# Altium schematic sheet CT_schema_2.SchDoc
size 461 x 327 mm
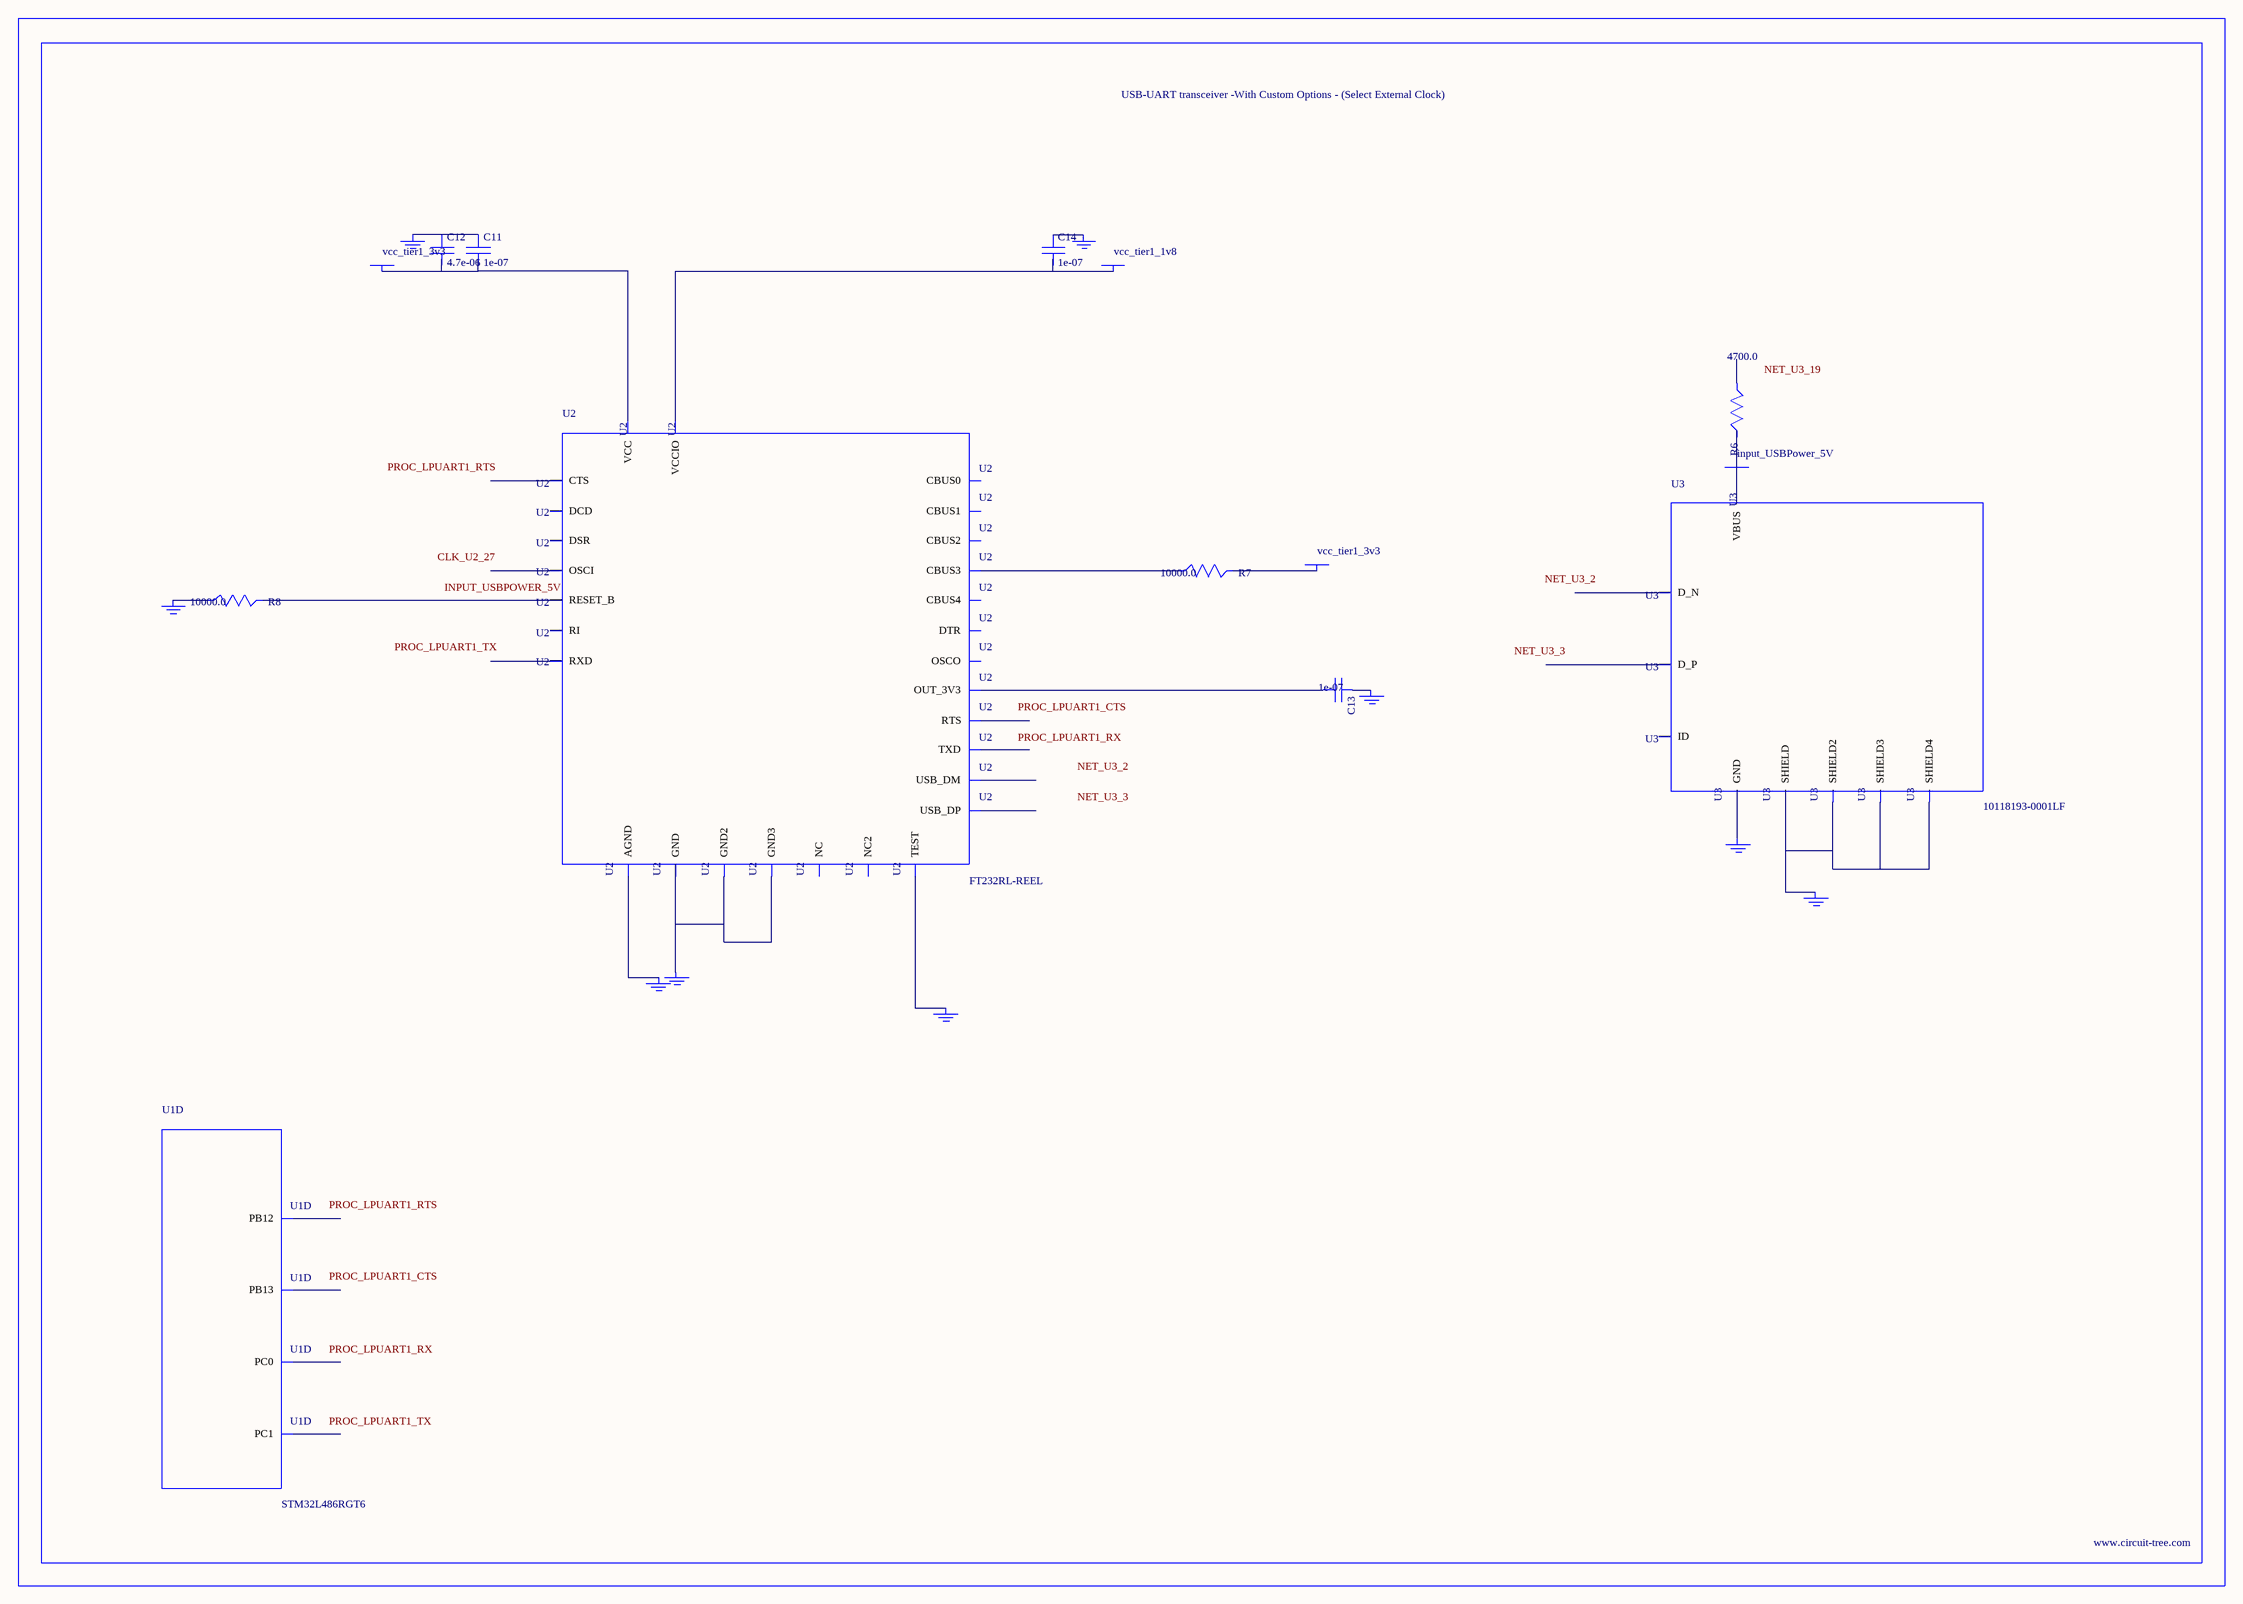
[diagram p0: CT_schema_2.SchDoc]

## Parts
BORDER1  (no value)
C11  1e-07  [C0402]
C12  4.7e-06  [C0805]
C13  1e-07  [C0402]
C14  1e-07  [C0402]
GND_INSTANCE_1_0  (no value)
GND_INSTANCE_1_1  (no value)
GND_INSTANCE_1_2  (no value)
GND_INSTANCE_1_3  (no value)
GND_INSTANCE_1_4  (no value)
GND_INSTANCE_1_5  (no value)
GND_INSTANCE_1_6  (no value)
GND_INSTANCE_1_7  (no value)
GND_INSTANCE_1_8  (no value)
POWER_INSTANCE_1_0  vcc_tier1_1v8
POWER_INSTANCE_1_1  vcc_tier1_3v3
POWER_INSTANCE_1_2  vcc_tier1_3v3
POWER_INSTANCE_1_3  input_USBPower_5V
R6  4700.0  [R0603]
R7  10000.0  [R0603]
R8  10000.0  [R0603]
U1  STM32L486RGT6  [LQFP64]  (part D of 7)
U2  FT232RL-REEL  [SSOP-28]
U3  10118193-0001LF  [FCI_10118193-0001LF]

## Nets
NetC11_1: C11.1 C12.1 GND_INSTANCE_1_3.0(GND)
NetC11_2: C11.2 C12.2 POWER_INSTANCE_1_2.0(PWR) U2.20(VCC)
NetC13_1: C13.1 GND_INSTANCE_1_1.0(GND)
NetC13_2: C13.2 U2.17(OUT_3V3)
NetC14_1: C14.1 GND_INSTANCE_1_0.0(GND)
NetC14_2: C14.2 POWER_INSTANCE_1_0.0(PWR) U2.4(VCCIO)
NetGND_INSTANCE_1_2_0: GND_INSTANCE_1_2.0(GND) R8.1
NetGND_INSTANCE_1_4_0: GND_INSTANCE_1_4.0(GND) U2.25(AGND)
NetGND_INSTANCE_1_5_0: GND_INSTANCE_1_5.0(GND) U2.26(TEST)
NetGND_INSTANCE_1_6_0: GND_INSTANCE_1_6.0(GND) U2.7(GND) U2.18(GND2) U2.21(GND3)
NetGND_INSTANCE_1_7_0: GND_INSTANCE_1_7.0(GND) U3.6(SHIELD) U3.7(SHIELD2) U3.8(SHIELD3) U3.9(SHIELD4)
NetGND_INSTANCE_1_8_0: GND_INSTANCE_1_8.0(GND) U3.5(GND)
NetPOWER_INSTANCE_1_1_0: POWER_INSTANCE_1_1.0(PWR) R7.2
NetPOWER_INSTANCE_1_3_0: POWER_INSTANCE_1_3.0(PWR) R6.2 U3.1(VBUS)
NetR7_1: R7.1 U2.14(CBUS3)
NetR8_2: R8.2 U2.19(RESET_B)

Not connected (* = marked no-connect by the designer): R6 1; U1 8(PC0) 9(PC1) 33(PB12) 34(PB13); U2 1(TXD) 2(DTR) 3(RTS) 5(RXD) 6(RI) 8(NC) 9(DSR) 10(DCD) 11(CTS) 12(CBUS4) 13(CBUS2) 15(USB_DP) 16(USB_DM) 22(CBUS1) 23(CBUS0) 24(NC2) 27(OSCI) 28(OSCO); U3 2(D_N) 3(D_P) 4(ID)

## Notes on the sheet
- Labels drawn without touching a wire or pin: CLK_U2_27, INPUT_USBPOWER_5V, NET_U3_2, NET_U3_3, NET_U3_19, PROC_LPUART1_CTS, PROC_LPUART1_RTS, PROC_LPUART1_RX, PROC_LPUART1_TX

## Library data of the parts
BORDER1 = BORDER_PAGE1
C11 C13 C14 = C0402C104K3RACTU
C12 = C0805C475K4RACTU
GND_INSTANCE_1_0-GND_INSTANCE_1_8 = GND
POWER_INSTANCE_1_0-POWER_INSTANCE_1_3 = PWR
R6 = RC0603JR-074K7L
R7 R8 = RC0603JR-0710KL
